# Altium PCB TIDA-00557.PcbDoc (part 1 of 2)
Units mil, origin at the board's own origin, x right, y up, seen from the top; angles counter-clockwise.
Board outline 3556 x 3500 mil, 2 copper layers (Top Layer, Bottom Layer), stack 62 mil thick; 145 components, 107 nets, 402 pads, 185 vias.
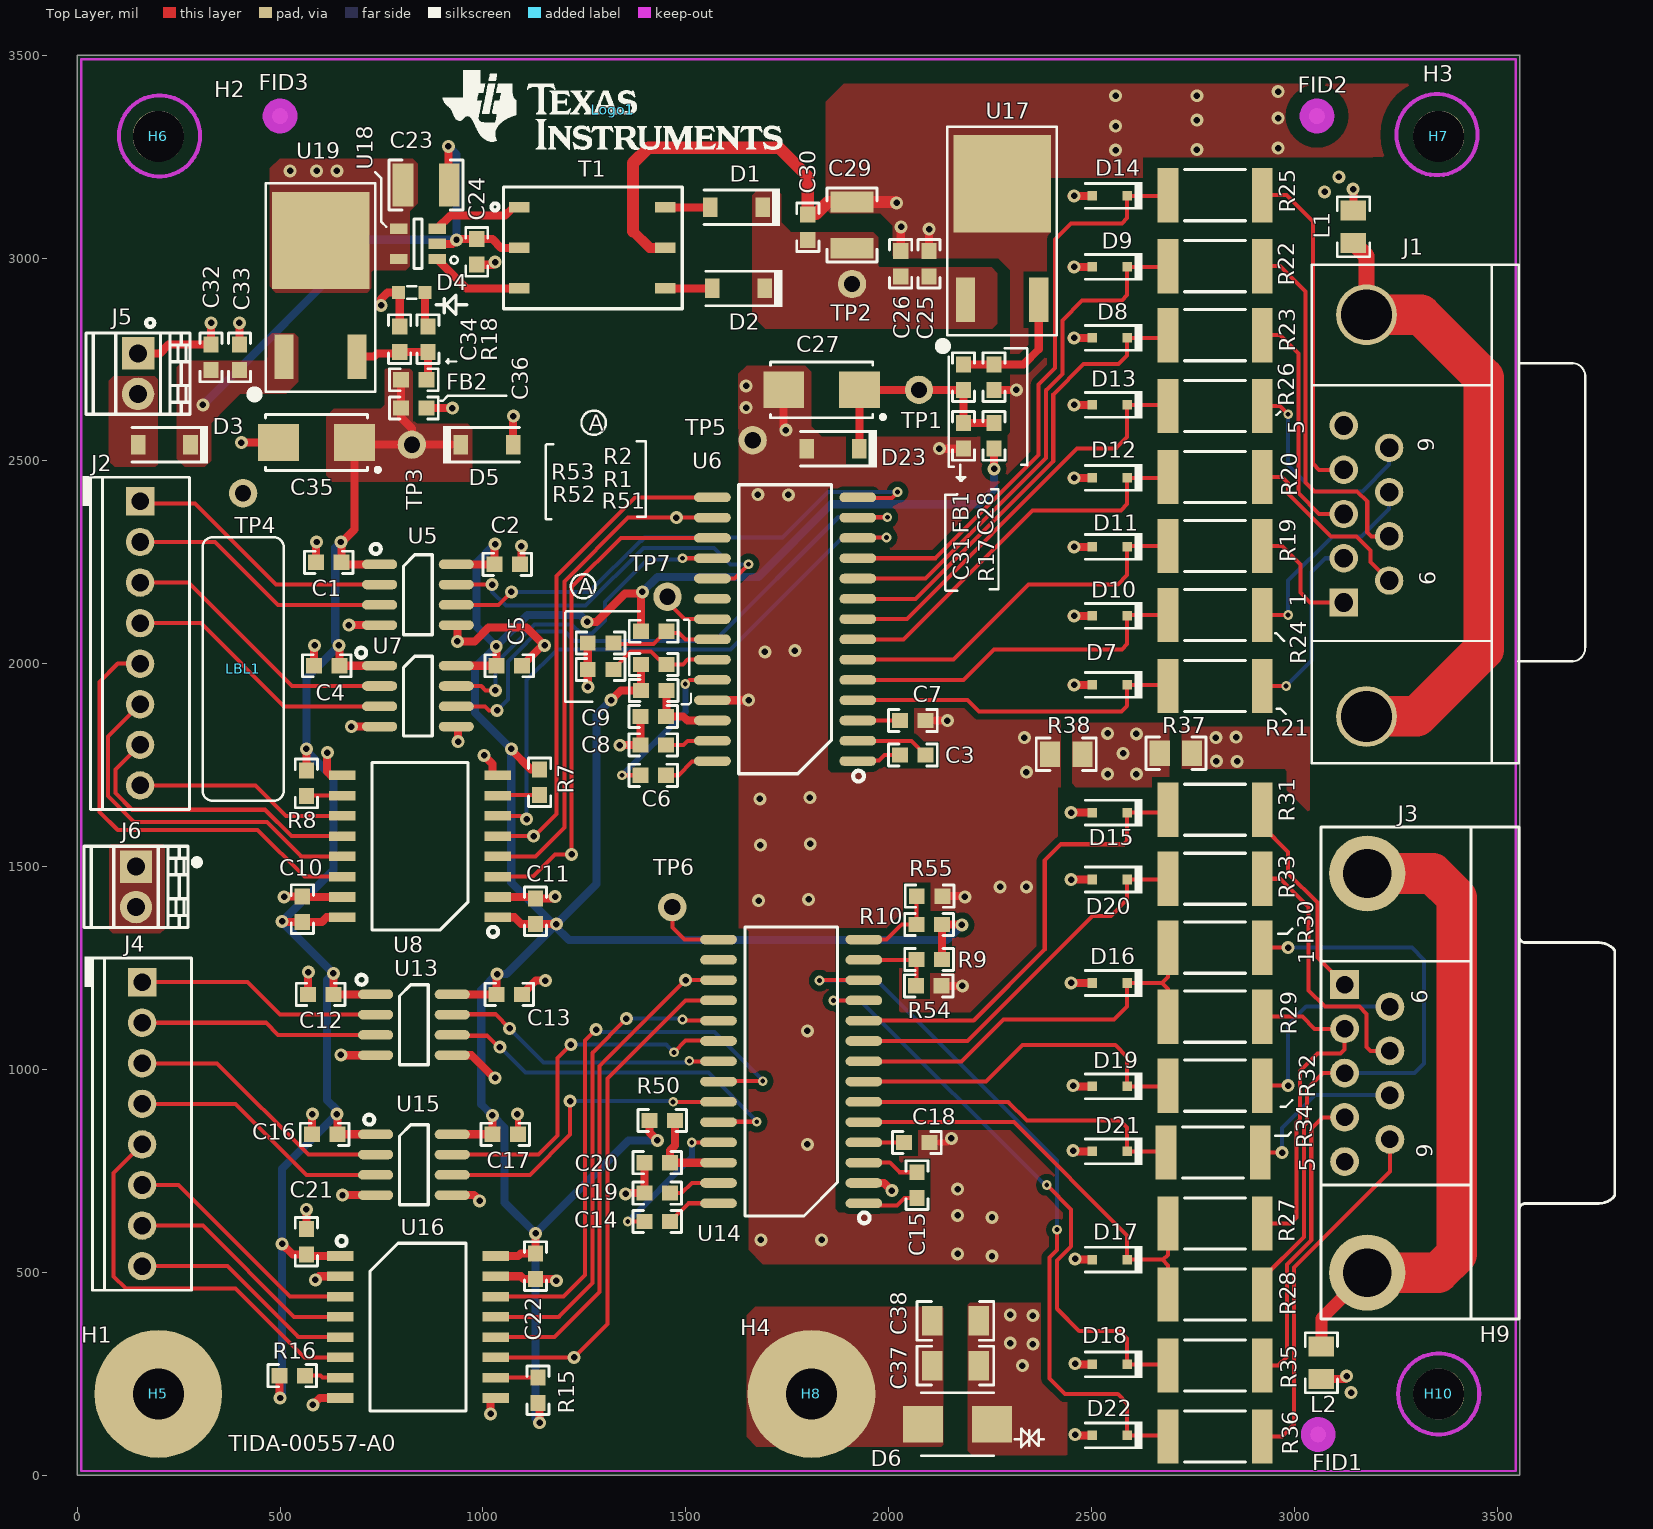
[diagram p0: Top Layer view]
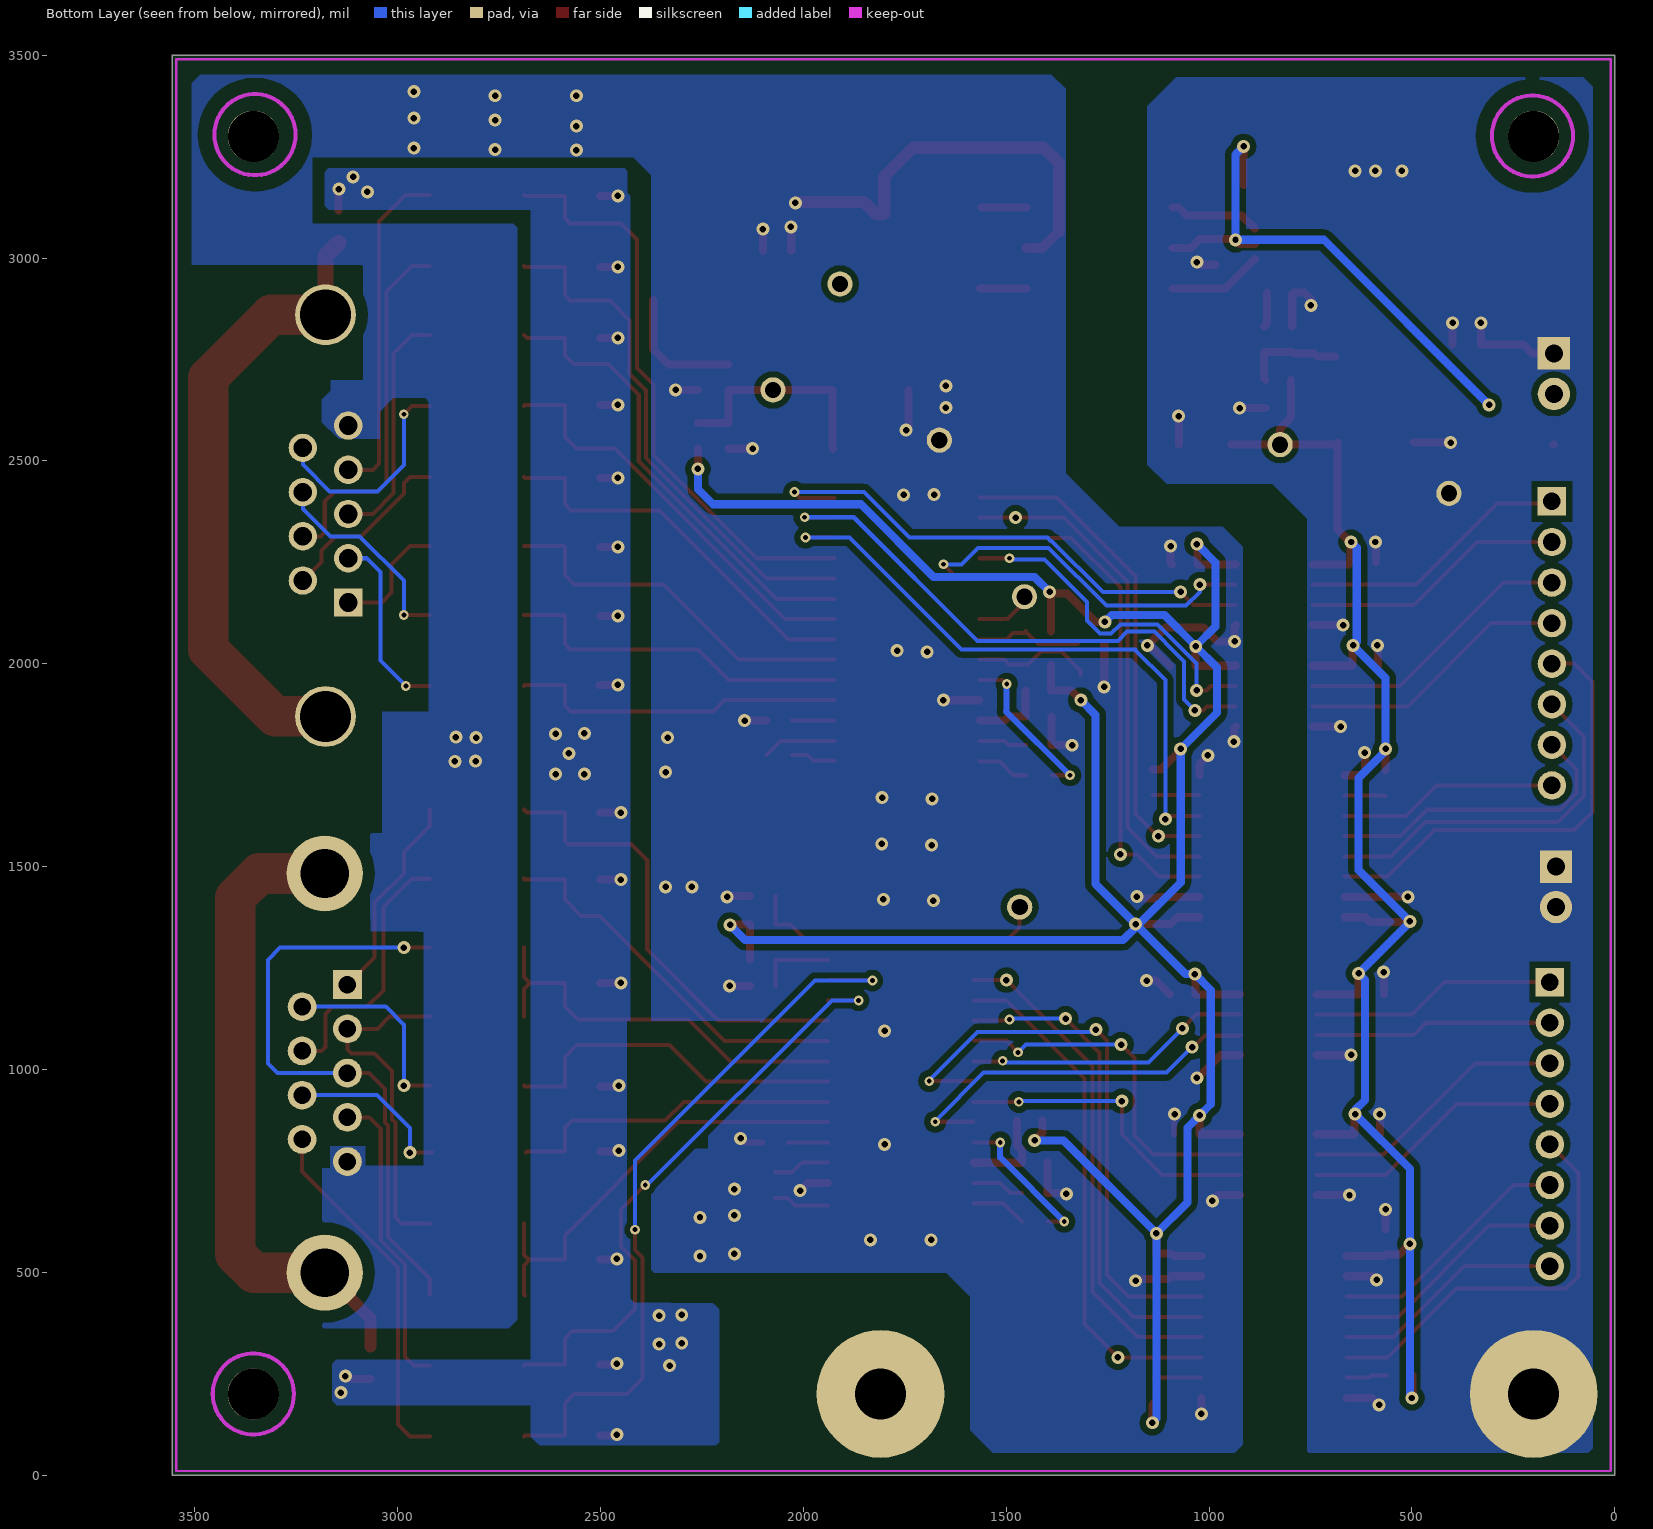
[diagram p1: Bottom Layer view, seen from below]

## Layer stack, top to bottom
Top Solder: solder mask 0.4, Solder Resist, Dk 3.5
Top Layer: signal copper 1.4
Dielectric1: core 59.2, FR-4, Dk 4.8
Bottom Layer: signal copper 1.4
Bottom Solder: solder mask 0.4, Solder Resist, Dk 3.5

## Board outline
0,0 3556,0 3556,3500 0,3500

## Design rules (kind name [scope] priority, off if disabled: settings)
AcuteAngle [All] p1: minimum=4.50000000000000E+0001 checktracksonly=FALSE
AssemblyTestPointUsage [All] p1: valid=2
Clearance Clearance_3 [InNet('NetJ3_10') vs InNet('GND2')] p1: gap=30
Clearance Clearance_2 [InNet('NetJ1_10') vs InNet('GND2')] p2: gap=30
Clearance Clearance_poly_earth [InPolygon vs InNetClass('earth')] p3: gap=100
Clearance "Bord edge_to_poly" [IsBoardOutline vs InPolygon] p4: gap=50
Clearance "MONT_HOLE_TO _POLY" [IsKeepOut vs InPolygon] p5: gap=35
Clearance Clearance_poly_to_all [InPolygon] p6: gap=15
Clearance "Clearance_Poly to Poly" [InPoly vs InPoly] p7: gap=25
Clearance [InPolygon vs (OnLayer('Keep-Out Layer'))] p8: gap=40
Clearance "Clearance_VIA TO VIA" [IsVia vs IsVia] p9: gap=8
Clearance "Clearance_Via to SMD" [IsVia vs IsSMTPin] p10: gap=8
Clearance Clearance_1 [All] p11: gap=8
ComponentClearance ComponentClearance_Logo [InComponentClass('Logo')] p1: gap=50 collisioncheckmode=3 verticalgap=10 showdistances=FALSE
ComponentClearance ComponentClearance_ScrewToNut [(HasFootprint('NY PMS 440 0025 PH')) vs (HasFootprint('Keystone_1902C'))] p2: gap=5 collisioncheckmode=3 verticalgap=10 showdistances=FALSE
ComponentClearance ComponentClearance_MountingHoles [InComponentClass('Mounting Holes')] p3: gap=250 collisioncheckmode=3 verticalgap=100000 showdistances=FALSE
ComponentClearance ComponentClearance_SmallPassives [HasFootprint('0201*') or HasFootprint('0402*') or HasFootprint('0508') or HasFootprint('0603*') or HasFootprint('0612') or HasFootprint('0805*') or HasFootprint('0815*') or HasFootprint('0830*') or HasFootprint('1206*') or HasFootprint('1210*') or HasFootprint('1808*') or HasFootprint('1812*') or HasFootprint('1825*') or HasFootprint('2010*') or HasFootprint('2220*') or HasFootprint('2225*') or HasFootprint('2512*') or HasFootprint('2728*') or HasFootprint('3518*') vs HasFootprint('0201*') or HasFootprint('0402*') or HasFootprint('0508') or HasFootprint('0603*') or HasFootprint('0612') or HasFootprint('0805*') or HasFootprint('0815*') or HasFootprint('0830*') or HasFootprint('1206*') or HasFootprint('1210*') or HasFootprint('1808*') or HasFootprint('1812*') or HasFootprint('1825*') or HasFootprint('2010*') or HasFootprint('2220*') or HasFootprint('2225*') or HasFootprint('2512*') or HasFootprint('2728*') or HasFootprint('3518*')] p4: gap=20 collisioncheckmode=3 verticalgap=10 showdistances=FALSE
ComponentClearance ComponentClearance_THtoSMT [IsThruComponent vs IsSMTComponent] p5: gap=100 collisioncheckmode=3 verticalgap=30 showdistances=FALSE
ComponentClearance ComponentClearance_THtoTH [IsThruComponent vs IsThruComponent] p6: gap=118.11 collisioncheckmode=3 verticalgap=30 showdistances=FALSE
ComponentClearance [All] p7: gap=40 collisioncheckmode=3 verticalgap=10 showdistances=FALSE
DiffPairsRouting [All] p1: maxlimit=100 minlimit=10 mostfreqgap=10 toplayer_minwidth=15 toplayer_maxwidth=15 toplayer_prefwidth=15 bottomlayer_minwidth=15 bottomlayer_maxwidth=15 bottomlayer_prefwidth=15 maxuncoupledlength=1000
FabricationTestPointUsage TestPointUsage [All] p1: valid=2 allowmultiple=FALSE
FabricationTestpoint Testpoint [All] p1: side=3 testpointundercomponent=TRUE minsize=40 maxsize=100 preferedsize=60 minholesize=0 maxholesize=40 preferedholesize=32 testpointgrid=1 allowsidetop=TRUE allowsidebottom=TRUE usegrid=TRUE gridtolerance=0.01
FanoutControl Fanout_LCC [IsLCC] p1: bgadir=Out bgaviamode=Centered fanoutstyle=Auto fanoutdirection=Alternating viagrid=1 // Fanout_LCC (Default Rule)
FanoutControl Fanout_BGA [IsBGA] p2: bgadir=Out bgaviamode=Centered fanoutstyle=Auto fanoutdirection=Alternating viagrid=1 // Fanout_BGA (Default Rule)
FanoutControl Fanout_Default [All] p4: bgadir=Out bgaviamode=Centered fanoutstyle=Auto fanoutdirection=Alternating viagrid=1 // Fanout_Default (Default Rule)
FanoutControl Fanout_Small [(CompPinCount < 5)] p5: bgadir=Out bgaviamode=Centered fanoutstyle=Auto fanoutdirection=OutThenIn viagrid=1 // Fanout_Small (Default Rule)
HoleSize [All] p1: absolutevalues=TRUE maxlimit=251 minlimit=7.8 maxpercent=80.000 minpercent=20.000
MinimumAnnularRing MinimumAnnularRing_ThermalPadVias [IsVia and InAnyComponent] p1: minimumring=5.91
MinimumAnnularRing [All] p2: minimumring=6
MinimumSolderMaskSliver MinimumSolderMaskSliver_Logo [InComponentClass('Logo') vs InComponentClass('Logo')] p1: minsoldermaskwidth=0.7
MinimumSolderMaskSliver [All] p2: minsoldermaskwidth=3.94
PlaneConnect [All] p1: planeconnectstyle=Direct reliefexpansion=10 reliefentries=4 reliefconductorwidth=10 reliefairgap=10
PolygonConnect [All] p1: connectstyle=Direct reliefconductorwidth=10 reliefentries=4 polygonreliefangle="90 Angle" airgapwidth=10
RoutingVias RoutingVias_PWR [InNetClass('Power')] p1: holewidth=16 width=32 viastyle="Through Hole" minholewidth=16 minwidth=32 maxholewidth=16 maxwidth=32
RoutingVias [(InNetClass('All Nets'))] p2: holewidth=12 width=24 viastyle="Through Hole" minholewidth=12 minwidth=24 maxholewidth=16 maxwidth=32
RoutingVias ThermalPadVias [IsVia and InAnyComponent] p3: holewidth=7.87 width=19.68 viastyle="Through Hole" minholewidth=7.87 minwidth=19.68 maxholewidth=12.99 maxwidth=23.62
SMDToCorner [All] p1: distance=30000
SilkToSilkClearance [All] p1: silktosilkclearance=5
SilkToSolderMaskClearance SilkscreenOverComponentPads [IsPad] p1 off: minsilkscreentomaskgap=5 clearancetoexposedcopper=TRUE
SolderMaskExpansion [All] p1: expansion=2.5
UnpouredPolygon [All] p1: allowunpoured=FALSE
Width Width_PWR [InNetClass('Power')] p1: maxlimit=100 minlimit=10 preferedwidth=20
Width [All] p2: maxlimit=100 minlimit=8 preferedwidth=8 checkconnectedcopper=TRUE
15 further rules are at their usual default settings.

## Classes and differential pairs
component class "Page4 Power Supply": C23 C24 C25 C26 C27 C28 C29 C30 C31 C32 C33 C34 C35 C36 C37 C38 D1 D2 D3 D4 D5 D6 D23 FB1 FB2 J5 R17 R18 T1 TP1 TP2 TP3 TP4 TP5 U17 U18 U19
component class "Page5 Hardware_ANSI-B": FID1 FID2 FID3 H1 H2 H3 H4 H5 H6 H7 H8 H9 H10 LBL1 Logo1 ZZ1 ZZ2 ZZ3 ZZ4
component class Logo: Logo1
component class "Page2 DTE-DCE": C1 C2 C3 C4 C5 C6 C7 C8 C9 C10 C11 D7 D8 D9 D10 D11 D12 D13 D14 J1 J2 J6 L1 R1 R2 R7 R8 R19 R20 R21 R22 R23 R24 R25 R26 R51 R52 R53 TP7 U5 U6 U7 U8
component class "Page3 DCE-DTE": C12 C13 C14 C15 C16 C17 C18 C19 C20 C21 C22 D15 D16 D17 D18 D19 D20 D21 D22 J3 J4 L2 R9 R10 R15 R16 R27 R28 R29 R30 R31 R32 R33 R34 R35 R36 R37 R38 R50 R54 R55 TP6 U13 U14 U15 U16
component class AssemblyNote: ZZ1 ZZ2 ZZ3 ZZ4
component class Label: LBL1
component class FiducialMark: FID1 FID2 FID3
component class "Mounting Holes": H1 H2 H3 H4 H9
net class Power: +5V +6V_VDC GND1 GND2 VCC1 VCC2

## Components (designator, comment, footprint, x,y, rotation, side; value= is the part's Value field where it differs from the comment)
C1 "C0603C104K5RACTU" 0603 620,2250 r180 top
C2 "C0603C104K5RACTU" 0603 1060,2245 r0 top
C3 "C0603C104K5RACTU" 0603 2060,1775 r0 top
C4 "C0603C104K5RACTU" 0603 615,1995 r180 top
C5 "C0603C104K5RACTU" 0603 1065,1995 r0 top
C6 "C0603C104K5RACTU" 0603 1420,1725 r180 top
C7 "C0603C104K5RACTU" 0603 2060,1860 r0 top
C8 "C0603C104K5RACTU" 0603 1420,1800 r180 top
C9 "C0603C104K5RACTU" 0603 1420,1870 r180 top
C10 "C0603C104K5RACTU" 0603 555,1395 r90 top
C11 "C0603C104K5RACTU" 0603 1130,1390 r90 top
C12 "C0603C104K5RACTU" 0603 600,1185 r180 top
C13 "C0603C104K5RACTU" 0603 1065,1185 r0 top
C14 "C0603C104K5RACTU" 0603 1430,625 r180 top
C15 "C0603C104K5RACTU" 0603 2070,715 r90 top
C16 "C0603C104K5RACTU" 0603 610,840 r180 top
C17 "C0603C104K5RACTU" 0603 1055,840 r0 top
C18 "C0603C104K5RACTU" 0603 2070,820 r0 top
C19 "C0603C104K5RACTU" 0603 1430,695 r180 top
C20 "C0603C104K5RACTU" 0603 1430,770 r180 top
C21 "C0603C104K5RACTU" 0603 565,575 r90 top
C22 "C0603C104K5RACTU" 0603 1130,515 r270 top
C23 "" 1210 860,3180 r0 top
C24 "" 0603 985,3015 r90 top
C25 "C1608X7R1C105K" 0603 2100,2986 r90 top
C26 "C0603C104K5RACTU" 0603 2030,2986 r90 top
C27 "293D475X9035C2TE3" 6032-28 1835,2675 r180 top
C28 "C1608X7R1C105K" 0603 2260,2706.5 r270 top
C29 "" 1210 1910,3081 r90 top
C30 "" 0603 1801,3076 r90 top
C31 "C0603C104K5RACTU" 0603 2185,2561.5 r270 top
C32 "C1608X7R1C105K" 0603 330,2755 r90 top
C33 "C0603C104K5RACTU" 0603 400,2755 r90 top
C34 "C1608X7R1C105K" 0603 795,2800 r90 top
C35 "293D475X9035C2TE3" 6032-28 590,2545 r180 top
C36 "C0603C104K5RACTU" 0603 830,2630 r0 top
C37 "202R18W102KV4E" 1206 2165,270 r180 top
C38 "202R18W102KV4E" 1206 2165,380 r180 top
D1 "B0520LW-7-F" SOD-123 1625,3125 r180 top
D2 "B0520LW-7-F" SOD-123 1630,2925 r180 top
D3 "B0520LW-7-F" SOD-123 215,2540 r180 top
D4 "LED_LG L29K-G2J1-24-Z" LED0603AA 825,2915 r0 top
D5 "MMSZ5228B-7-F" sod-123 1010,2540 r0 top
D6 "SMBJ18CA" DIO_SMB_BIAAAA 2170,125 r180 top
D7 "CDSOD323-T12C" sod-323 2545,1947.99 r180 top
D8 "CDSOD323-T12C" sod-323 2545,2802.99 r180 top
D9 "CDSOD323-T12C" sod-323 2545,2977.99 r180 top
D10 "CDSOD323-T12C" sod-323 2545,2117.99 r180 top
D11 "CDSOD323-T12C" sod-323 2545,2287.99 r180 top
D12 "CDSOD323-T12C" sod-323 2545,2457.99 r180 top
D13 "CDSOD323-T12C" sod-323 2545,2637.99 r180 top
D14 "CDSOD323-T12C" sod-323 2545,3152.99 r180 top
D15 "CDSOD323-T12C" sod-323 2545,1632.99 r180 top
D16 "CDSOD323-T12C" sod-323 2545,1212.99 r180 top
D17 "CDSOD323-T12C" sod-323 2545,530.99 r180 top
D18 "CDSOD323-T12C" sod-323 2545,272.99 r180 top
D19 "CDSOD323-T12C" sod-323 2545,957.99 r180 top
D20 "CDSOD323-T12C" sod-323 2545,1467.99 r180 top
D21 "CDSOD323-T12C" sod-323 2545,797.99 r180 top
D22 "CDSOD323-T12C" sod-323 2545,97.99 r180 top
D23 "MMSZ5228B-7-F" sod-123 1863,2530 r180 top
FB1 "1000 OHM" 0603 2185,2706.5 r270 top
FB2 "1000 OHM" 0603 830,2700 r180 top
FID1 "Fiducial" Fiducial10-20 3059,100 r90 top
FID2 "Fiducial" Fiducial10-20 3056,3350 r90 top
FID3 "Fiducial" Fiducial10-20 500,3350 r90 top
H1 "NY PMS 440 0025 PH" "NY PMS 440 0025 PH"#1 200,200 r0 top
H2 "NY PMS 440 0025 PH" "NY PMS 440 0025 PH"#2 200,3300 r0 top
H3 "NY PMS 440 0025 PH" "NY PMS 440 0025 PH"#2 3356,3300 r0 top
H4 "NY PMS 440 0025 PH" "NY PMS 440 0025 PH"#1 1810,200 r0 top
H5 "1902C" Keystone_1902C 200,200 r0 top
H6 "1902C" Keystone_1902C 200,3300 r0 top
H7 "1902C" Keystone_1902C 3356,3300 r0 top
H8 "1902C" Keystone_1902C 1810,200 r0 top
H9 "NY PMS 440 0025 PH" "NY PMS 440 0025 PH"#2 3356,200 r0 top (schematic designator H3)
H10 "1902C" Keystone_1902C 3356,200 r0 top
J1 "CONN_DB9_RA" DB9_RA 3122,2151 r90 top
J2 "1725711" CONN_1725711 155,2050 r270 top
J3 "182-009-213R171" NORCOMP_182-009-213R171 3554,991 r270 top
J4 "1725711" CONN_1725711 160,865 r270 top
J5 "CON-OSTVN02A150" CN2_MTB_P100_PD80_D1.1_S5.54X6.5_STACK 150,2715 r270 top
J6 "CON-OSTVN02A150" CN2_MTB_P100_PD80_D1.1_S5.54X6.5_STACK 145,1450 r270 top
L1 "BLM21AG121SN1D" 0805_HV 3146,3077 r90 top
L2 "BLM21AG121SN1D" 0805_HV 3067,277 r270 top
LBL1 "Size: 0.65\" x 0.20 \"" Label_650x200 409,1987 r90 top
Logo1 "Texas Instruments" TI_Stacked_Overlay_Small 1320,3365 r0 top
R1 "CRCW060310K0FKEA" 0603 1421,1998 r180 top
R2 "CRCW060310K0FKEA" 0603 1421,2080 r180 top
R7 "CRCW060310K0FKEA" 0603 1140,1708 r90 top
R8 "CRCW060310K0FKEA" 0603 565,1705 r90 top
R9 "CRCW060310K0FKEA" 0603 2100,1271 r0 top
R10 "CRCW060310K0FKEA" 0603 2100,1357 r0 top
R15 "CRCW060310K0FKEA" 0603 1136,209 r270 top
R16 "CRCW060310K0FKEA" 0603 530,245 r180 top
R17 "CRCW06030000Z0EA" 0603 2260,2561.5 r270 top
R18 "CRCW0603300RJNEA" 0603 865,2800 r270 top
R19 "RPC2512JT22R0" 2512 2805,2290 r0 top
R20 "RPC2512JT22R0" 2512 2805,2460 r0 top
R21 "RPC2512JT22R0" 2512 2805,1945 r0 top
R22 "RPC2512JT22R0" 2512 2805,2980 r0 top
R23 "RPC2512JT22R0" 2512 2805,2810 r0 top
R24 "RPC2512JT22R0" 2512 2805,2120 r0 top
R25 "RPC2512JT22R0" 2512 2805,3155 r0 top
R26 "RPC2512JT22R0" 2512 2805,2635 r0 top
R27 "DNP" 2512 2805,620 r0 top
R28 "RPC2512JT22R0" 2512 2805,445 r0 top
R29 "RPC2512JT22R0" 2512 2805,1130 r0 top
R30 "DNP" 2512 2805,1300 r0 top
R31 "RPC2512JT22R0" 2512 2805,1640 r180 top
R32 "RPC2512JT22R0" 2512 2805,960 r180 top
R33 "RPC2512JT22R0" 2512 2805,1470 r180 top
R34 "RPC2512JT22R0" 2512 2800,795 r180 top
R35 "RPC2512JT22R0" 2512 2805,270 r180 top
R36 "RPC2512JT22R0" 2512 2805,95 r180 top
R37 "CRCW08050000Z0EA" 0805_HV 2708.19,1779.29 r180 top
R38 "CRCW08050000Z0EA" 0805_HV 2438,1777 r0 top
R50 "CRCW06030000Z0EA" 0603 1442,874 r180 top
R51 "CRCW06030000Z0EA" 0603 1421,1934 r0 top
R52 "CRCW060310K0FKEA" 0603 1290,1986 r180 top
R53 "CRCW060310K0FKEA" 0603 1290,2051 r0 top
R54 "CRCW060310K0FKEA" 0603 2099,1206 r180 top
R55 "CRCW060310K0FKEA" 0603 2101,1427 r180 top
T1 "TRNSFMR 760390014" 760390015 1090,3125 r0 top
TP1 "TP-040_RND" TP-040_RND 2075,2675 r0 top
TP2 "TP-040_RND" TP-040_RND 1910,2936 r0 top
TP3 "TP-040_RND" TP-040_RND 825,2540 r0 top
TP4 "TP-040_RND" TP-040_RND 409,2420 r0 top
TP5 "TP-040_RND" TP-040_RND 1665,2551 r0 top
TP6 "TP-040_RND" TP-040_RND 1467,1400 r0 top
TP7 "TP-040_RND" TP-040_RND 1455,2165 r0 top
U5 "ISO7321CD" D0008A_N 840,2170 r0 top
U6 "TRS3243EIDWR" DW0028A_N 1745,2085 r180 top
U7 "ISO7321CD" D0008A_N 840,1920 r0 top
U8 "ISO7341CDWR" DW0016B_HV 845,1550 r180 top
U13 "ISO7321CD" D0008A_N 830,1110 r0 top
U14 "TRSF3238EIDWR" DW0028A_N 1760,995 r180 top
U15 "ISO7321CD" D0008A_N 830,765 r0 top
U16 "ISO7341CDWR" DW0016B_HV 840,365 r0 top
U17 "TPS7A6533QKVURQ1" KVU_1 2280,3040 r0 top
U18 "SN6501DBV" DBV0005A_N 840,3035 r180 top
U19 "TPS7A6533QKVURQ1" KVU_1 600,2900 r0 top
ZZ1 "This Assembly Note is for PCB labels only" AssemblyNoteLabel 205,5165 r0 top
ZZ2 "These assemblies are ESD sensitive, ESD precautions shall be observed." AssemblyNote 200,5075 r0 top
ZZ3 "These assemblies must be clean and free from flux and all contaminants. Use of no clean flux is not acceptable." AssemblyNote 200,4990 r0 top
ZZ4 "These assemblies must comply with workmanship standards IPC-A-610 Class 2, unless otherwise specified." AssemblyNote 200,4910 r0 top

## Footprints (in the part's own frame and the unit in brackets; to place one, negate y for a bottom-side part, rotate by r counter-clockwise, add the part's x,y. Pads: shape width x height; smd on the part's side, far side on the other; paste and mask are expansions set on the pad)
0603 [mm] "0603 from SM-752 data"
  rect 1x0.95 smd: 1(-0.8,0) 2(0.8,0)
  silkscreen extent -1.52,-0.69 1.52,0.69, body extent -0.87,-0.47 0.87,0.47, height 0.85
0805_HV [mil] "0805 with 30mil clearance between pads"
  rect 50x63 smd: 1(-40,0) 2(40,0)
  silkscreen extent -74,-40 74,40, body extent -43,-29 43,29, height 43
1206 [mm] "1206 from SM-752 data"
  rect 1.3x1.85 smd: 1(-1.45,0) 2(1.45,0)
  silkscreen extent -2.4,-1.21 2.4,1.21, body extent -1.7,-0.9 1.7,0.9, height 1.35
1210 [mm] "1210 from SM-752 data"
  rect 1.3x2.7 smd: 1(-1.45,0) 2(1.45,0)
  silkscreen extent -2.32,-1.57 2.32,1.57, body extent -1.7,-1.35 1.7,1.35, height 1.35
2512 [mm] "Chip Resistor, Body 6.3x3.2mm, IPC Medium Density"
  rect 1.3x3.4 smd: 1(-2.95,0) 2(2.95,0)
  silkscreen extent -1.9,-1.6 1.9,1.6, body extent -3.22,-1.67 3.22,1.67, height 0.71
6032-28 [mm] "Medium Density IPC based on Vishay Sprague 293D datasheet."
  rect 2.55x2.3 smd: 1(-2.375,0) 2(2.375,0)
  silkscreen extent -3.96,-1.75 3.2,1.82, body extent -3.15,-1.75 3.15,1.75, height 2.8
760390015 [mm]
  rect 1.27x0.66 smd: 1(0,0) 2(0,-2.54) 3(0,-5.08) 4(9.14,-5.08) 5(9.14,-2.54) 6(9.14,0)
  silkscreen extent -1.75,-6.35 10.2,1.27, body extent -1,-6.4 10.2,1.2, height 4.2
AssemblyNote [mil] "Assembly Note"
AssemblyNoteLabel [mil] "Assembly Note for PCB Labels"
CN2_MTB_P100_PD80_D1.1_S5.54X6.5_STACK [mil]
  rect 80x80 / inner round 80 / far side rect 80x80 hole 44: 1(-50,0)
  round 80 hole 44: 2(50,0)
  silkscreen extent -135,-128 100,128
CONN_1725711 [mm] "Phoenix Contact"
  rect 1.78x1.78 hole 1.1: 1(-8.89,0)
  round 1.78 hole 1.1: 2(-6.35,0) 3(-3.81,0) 4(-1.27,0) 5(1.27,0) 6(3.81,0) 7(6.35,0) 8(8.89,0)
  silkscreen extent -10.49,-3.6 10.4,3.1, body extent -10.39,-3.1 10.39,3.1, height 8.52
D0008A_N [mm] "SOIC, 8-Leads, Body 4.9x3.9mm, Pitch 1.27mm, IPC Medium Density"
  oval 2.2x0.6 smd: 1(-2.4,1.905) 2(-2.4,0.635) 3(-2.4,-0.635) 4(-2.4,-1.905) 5(2.4,-1.905) 6(2.4,-0.635) 7(2.4,0.635) 8(2.4,1.905)
  silkscreen extent -0.9,-2.5 0.9,2.5, body extent -3,-2.45 3,2.45, height 1.63
DB9_RA [mil]
  rect 70x70 hole 46: 1(0,0)
  round 70 hole 46: 2(109,0) 3(218,0) 4(327,0) 5(436,0) 6(54,-112) 7(163,-112) 8(272,-112) 9(381,-112)
  round 150 hole 125: 10(709,-56) 11(-281,-56)
  silkscreen extent -396,-595 832,79
DBV0005A_N [mm] "SOT23, 5-Leads, Body 2.9x1.6mm, Pitch 0.95mm, Lead Span 2.8mm, IPC Medium Density"
  rect 1.1x0.65 smd: 1(-1.2,0.95) 2(-1.2,0) 3(-1.2,-0.95) 4(1.2,-0.95) 5(1.2,0.95)
  silkscreen extent -0.25,-1.55 0.25,1.55, body extent -1.42,-1.46 1.42,1.46, height 1.08
DIO_SMB_BIAAAA [mm]
  rect 2.5x2.3 smd: 1(-2.15,0) 2(2.15,0)
  silkscreen extent -5.41,-1.97 2.29,1.97
DW0016B_HV [mm] "High voltage version of DW0016B"
  rect 1.65x0.6 smd: 1(-4.875,4.445) 2(-4.875,3.175) 3(-4.875,1.905) 4(-4.875,0.635) 5(-4.875,-0.635) 6(-4.875,-1.905) 7(-4.875,-3.175) 8(-4.875,-4.445) 9(4.875,-4.445) 10(4.875,-3.175) 11(4.875,-1.905) 12(4.875,-0.635) 13(4.875,0.635) 14(4.875,1.905) 15(4.875,3.175) 16(4.875,4.445)
  silkscreen extent -3,-5.25 3,5.25, body extent -5.14,-5.13 5.14,5.13, height 2.5
DW0028A_N [mm] "SOIC, 28-Leads, Body 17.9x7.5mm, Pitch 1.27mm, IPC Medium Density"
  oval 2.3x0.6 smd: 1(-4.55,8.255) 2(-4.55,6.985) 3(-4.55,5.715) 4(-4.55,4.445) 5(-4.55,3.175) 6(-4.55,1.905) 7(-4.55,0.635) 8(-4.55,-0.635) 9(-4.55,-1.905) 10(-4.55,-3.175) 11(-4.55,-4.445) 12(-4.55,-5.715) 13(-4.55,-6.985) 14(-4.55,-8.255) 15(4.55,-8.255) 16(4.55,-6.985) 17(4.55,-5.715) 18(4.55,-4.445) 19(4.55,-3.175) 20(4.55,-1.905) 21(4.55,-0.635) 22(4.55,0.635) 23(4.55,1.905) 24(4.55,3.175) 25(4.55,4.445) 26(4.55,5.715) 27(4.55,6.985) 28(4.55,8.255)
  silkscreen extent -2.9,-9.05 2.9,9.05, body extent -5.16,-8.95 5.16,8.95, height 2.55
Fiducial10-20 [mm]
  round 1 smd mask+0.5: 1(0,0)
  Top Layer keep-out circle w1.178: c0,0 r0.5
Keystone_1902C [mil] "Hex Standoff, 4-40 threaded, nylon"
  round 1 on Mech3: 0(0,0)
  body extent -145,-126 146,126, height 501
KVU_1 [mm]
  rect 1.2x2.8 smd: 1(-2.29,-3.635) 3(2.29,-3.635)
  rect 6.096x6.096 smd: 2(0,3.635)
  silkscreen extent -3.77,-6.58 3.43,7.22
Label_650x200 [mil] "Thermal Transfer Label"
  round 1 on Mech13: 0(0,0)
  silkscreen extent -325,-100 325,100, body extent -326,-101 326,101, height 1
LED0603AA [mil]
  rect 32x32 smd: 1(-32.48,0) 2(32.48,0)
  silkscreen extent -11,-53 135,16
NORCOMP_182-009-213R171 [mm] "Connector; D Subminiature 9 Position; Right Angle"
  rect 1.8x1.8 hole 1.092: 1(-5.54,-10.92)
  round 1.8 hole 1.092: 2(-2.77,-10.92) 3(0,-10.92) 4(2.77,-10.92) 5(5.54,-10.92) 6(-4.155,-8.08) 7(-1.385,-8.08) 8(1.385,-8.08) 9(4.155,-8.08)
  round 4.76 hole 3.05: 10(-12.495,-9.5) 11(12.495,-9.5)
  silkscreen extent -15.4,-12.4 15.4,6, body extent -15.41,-12.98 15.41,6.1, height 12.55
"NY PMS 440 0025 PH"#1 [mm] "4-40 nylon screw and mounting hole"
  round 8 hole 3.2: 1(0,0)
  body extent -3.3,-3.3 3.3,3.3, height 2.69
"NY PMS 440 0025 PH"#2 [mm] "4-40 nylon screw and mounting hole"
  round 3.2 hole 3.2 unplated mask+0.127: 1(0,0)
  body extent -3.3,-3.3 3.3,3.3, height 2.69
SOD-123 [mm] "On Semi recommended land pattern"
  rect 0.915x1.22 smd: 1(-1.637,0) 2(1.637,0)
  silkscreen extent -2.74,-1.17 2.03,1.17, body extent -1.93,-0.9 1.93,0.9, height 1.35
sod-123 [mm] "On Semi recommended land pattern"
  rect 0.915x1.22 smd: 1(-1.637,0) 2(1.637,0)
  silkscreen extent -2.74,-1.17 2.03,1.17, body extent -1.93,-0.9 1.93,0.9, height 1.35
sod-323 [mm] "NXP recommended land pattern"
  rect 0.6x0.6 smd paste-0.05: 1(-1.1,0) 2(1.1,0)
  silkscreen extent -2.06,-0.86 1.53,0.86, body extent -1.3,-0.67 1.3,0.68, height 1.1
TI_Stacked_Overlay_Small [mil]
  silkscreen extent -418,-98 418,98
TP-040_RND [mil]
  round 70 / inner round 62 / far side round 62 hole 40: 1(0,0)

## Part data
C1 C2 C3 C4 C5 C6 C7 C8 C9 C10 C11 C12 C13 C14 C15 C16 C17 C18 C19 C20 C21 C22 C26 C31 C33 C36: "CAP, CERM, 0.1uF, 50V, +/-10%, X7R, 0603"
C23 C29: library part GMK325AB7106MM-T, "CAP, CERM, 10uF, 35V, +/-20%, X7R, 1210"
C24 C30: library part C0603C104K5RACTU, "CAP, CERM, 0.1uF, 50V, +/-10%, X7R, 0603"
C25 C28 C32 C34: "CAP, CERM, 1uF, 16V, +/-10%, X7R, 0603"
C27 C35: "CAP, TA, 4.7uF, 35V, +/-10%, 1.9 ohm, SMD"
C37 C38: "CAP, CERM, 1000pF, 2KV 10% X7R 1206"
D1 D2 D3: library part MBR0520LT1G, "Diode, Schottky, 20V, 0.5A, SOD-123"
D4: "LED SmartLED Green 570NM"
D5 D23: library part 1SMB5915BT3G, "DIODE ZENER 3.9V 500MW SOD123"
D6: "TVS 18 VOLT 600 WATT BI-DIR SMB"
D7 D8 D9 D10 D11 D12 D13 D14 D15 D16 D17 D18 D19 D20 D21 D22: library part CDSOD323-T15SC, "Diode, TVS, ARRAY, 19V, SOD323"
FB1 FB2: library part MMZ1608B102C, "FERRITE CHIP 1000 OHM 300MA 0603"
FID1 FID2 FID3: "Fiducial mark.  There is nothing to buy or mount."
H1 H2 H3 H4 H9: "Machine Screw, Round, #4-40 x 1/4, Nylon, Philips panhead"
H5 H6 H7 H8 H10: "Standoff, Hex, 0.5\"L #4-40 Nylon"
J1: "Connector, 9-pin D, Right Angle, Male"
J2 J4: "Terminal Block, 8x1, 2.54 mm, TH"
J3: "CONN DB9 FEMALE R/A SOLDER TH"
J5 J6: "CONN TERM BLOCK 2.54MM 2POS PCB"
L1 L2: "Ferrite Bead, 120 ohm @ 100 MHz, 0.8 A, 0805"
LBL1: library part THT-14-423-10, "Thermal Transfer Printable Labels, 0.650\" W x 0.200\" H - 10,000 per roll"
Logo1: library part TI_Logo, "Texas Instrument Corporate Signature"
R1 R2 R7 R8 R9 R10 R15 R16 R52 R53 R54 R55: "RES, 10.0k ohm, 1%, 0.1W, 0603"
R17: "RES, 0 ohm, 5%, 0.1W, 0603"
R18: "RES, 300 ohm, 5%, 0.1W, 0603"
R19 R20 R21 R22 R23 R24 R25 R26 R28 R29 R31 R32 R33 R34 R35 R36: library part CRCW251210R0FKEG, "RES SMD 22 OHM 5% 1.5W 2512"
R27 R30: library part CRCW251210R0FKEG
R37 R38: "RES, 0, 5%, 0.125 W, 0805"
R50 R51: "RES, 0, 5%, 0.1 W, 0603"
T1: library part "TRNSFMR 760390015", "Transformer 475uH SMD"
TP1 TP2 TP3 TP4 TP5 TP6 TP7: "Test Point, O.040 Hole"
U5 U7 U13 U15: "IC, ISOLATOR DGTL 2CH 1/1, SOIC-8, ROHS"
U6: "3-V to 5.5-V Multichannel RS-232 Line Driver / Receiver with ±15-kV IEC ESD Protection, -40 to 85 degC, 28-Pin SOIC (DW), Green (RoHS & no Sb/Br)"
U8 U16: "Robust EMC, Low Power, Quad-Channel Digital Isolators, DW0016B"
U14: "3-V to 5.5-V Multichannel RS-232 Line Driver / Receiver with ±15-kV ESD (HBM) Protection, -40 to 85 degC, 28-Pin SOIC (DW),  Green (RoHS & no Sb/Br)"
U17 U19: "IC, 300-mA 40-V LOW-DROPOUT REGULATOR WITH 25-uA QUIESCENT CURRENT"
U18: "Transformer Driver for Isolated Power Supplies, DBV0005A"
ZZ1: library part AssemblyNoteLabel
ZZ2 ZZ3 ZZ4: library part AssemblyNote

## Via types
v1: diameter 32, hole 16, Top Layer to Bottom Layer, 163 vias
v2: diameter 24, hole 12, Top Layer to Bottom Layer, 22 vias

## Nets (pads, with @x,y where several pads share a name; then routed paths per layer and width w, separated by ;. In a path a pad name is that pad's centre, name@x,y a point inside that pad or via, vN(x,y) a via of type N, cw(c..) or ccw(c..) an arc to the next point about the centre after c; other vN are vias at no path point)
+5V: C23.2 C24.2 C32.1 C33.1 D3.1 T1.2 U18.2 U19.1 | length 1343.3
  Top Layer w20: U18.2@887.24,3035 925,3035 v1(935,3045) 936.5,3046.5 C24.2@985,3046.5 1023.5,3046.5 1045,3025 T1.2@1090,3025 ; C23.2@915,3180 v1(915,3275)
  Bottom Layer w20: v1(310,2638) 717,3045 v1(935,3045) 935,3255 v1(915,3275)
+6V_VDC: C25.1 C26.1 C29.1 C30.1 D1.1 D2.1 TP2.1 U17.1
CTS_IN: D10.1 R24.1 U6.5 | length 871.8
  Top Layer w10: U6.5@1924.13,1960 2185,1960 2260,2035 2575,2035 2588.31,2048.31 D10.1@2588.31,2117.99 2590.32,2120 R24.1@2688.86,2120
CTS_IN_1: U6.18 U7.7 | length 856.2
  Top Layer w10: U7.7@934.49,1945 996,1945 1007,1934 v1(1031,1934) ; v2(1492,2260) U6.18@1565.87,2260
  Bottom Layer w10: v1(1031,1934) 1031,2000.46 1044.54,2014 1045.01,2014 1062,2030.99 1062,2031.46 1127.54,2097 1219,2097 1242,2074 1269.01,2074 1301,2105.99 1301,2152 1406,2257 1489,2257 v2(1492,2260)
CTS_OUT: D21.1 R34.2 U14.6 | length 830.9
  Top Layer w10: U14.6@1939.13,920 2295,920 2341,874 2571,874 2588.31,856.69 D21.1@2588.31,797.99 2680.87,797.99 R34.2@2683.86,795
CTS_OUT_1: U14.23 U15.6 | length 781.2
  Top Layer w10: U15.6@924.49,740 1116,740 1215,839 v1(1215,922) ; v2(1469,920) U14.23@1580.87,920
  Bottom Layer w10: v1(1215,922) 1467,922 v2(1469,920)
CTSIN: J2.3 U7.2 | length 696.1
  Top Layer w10: J2.3@155,2200 275,2200 530,1945 U7.2@745.51,1945
CTSOUT: J4.4 U15.3 | length 648
  Top Layer w10: J4.4@160,915 390,915 565,740 U15.3@735.51,740
DCD_IN: D11.1 R19.1 U6.6 | length 921.5
  Top Layer w10: U6.6@1924.13,2010 2160,2010 2345,2195 2565,2195 2588.31,2218.31 D11.1@2588.31,2287.99 2590.32,2290 R19.1@2688.86,2290
DCD_IN_1: U6.17 U8.3 | length 1273.6
  Top Layer w10: U8.3@1024.13,1475 1123,1475 1178,1530 v1(1219,1530) 1219,2189 1340,2310 U6.17@1565.87,2310
DCD_OUT: D15.1 R31.2 U14.10 | length 1134.8
  Top Layer w10: U14.10@1939.13,1120 2210,1120 2385,1295 2385,1515 2425,1555 2580,1555 2588.31,1563.31 D15.1@2588.31,1632.99 2681.85,1632.99 R31.2@2688.86,1640
DCD_OUT_1: U14.19 U16.13 | length 1201
  Top Layer w10: U16.13@1019.13,390 1187,390 1270,473 1270,1041 v1(1354,1125) ; v2(1492,1123) 1495,1120 U14.19@1580.87,1120
  Bottom Layer w10: v1(1354,1125) 1490,1125 v2(1492,1123)
DCDIN: J2.5 U8.14 | length 1115.8
  Top Layer w10: J2.5@155,2000 100,2000 55,1955 55,1635 100,1590 445,1590 560,1475 U8.14@665.87,1475
DCDOUT: J4.7 U16.4 | length 594.1
  Top Layer w10: J4.7@160,615 310,615 535,390 U16.4@660.87,390
DSR_IN: D12.1 R20.1 U6.7 | length 968.3
  Top Layer w10: U6.7@1924.13,2060 2037,2060 2355,2378 2573,2378 2588.31,2393.31 D12.1@2588.31,2457.99 2686.85,2457.99 R20.1@2688.86,2460
DSR_IN_1: U6.16 U8.4 | length 1243.2
  Top Layer w10: U8.4@1024.13,1525 1130,1525 1201,1596 1201,2203 1358,2360 v1(1477,2360) U6.16@1565.87,2360
DSR_OUT: D19.1 R32.2 U14.7 | length 872.6
  Top Layer w10: U14.7@1939.13,970 2240,970 2330,1060 2558.84,1060 2588.31,1030.53 D19.1@2588.31,957.99 2686.85,957.99 R32.2@2688.86,960
DSR_OUT_1: U14.22 U16.14 | length 1444.9
  Top Layer w10: U16.14@1019.13,440 1199,440 1252,493 1252,1071 v1(1279,1098) ; U14.22@1580.87,971 v2(1690,971)
  Bottom Layer w10: v1(1279,1098) 1285,1092 1571,1092 1690,973 v2(1690,971)
DSRIN: J2.6 U8.13 | length 910.3
  Top Layer w10: J2.6@155,1900 76,1821 76,1674 140,1610 467.37,1610 552.37,1525 U8.13@665.87,1525
DSROUT: J4.6 U16.3 | length 614.8
  Top Layer w10: J4.6@160,715 250,715 525,440 U16.3@660.87,440
DTE_RX: D7.1 R21.1 U6.4 | length 835.2
  Top Layer w10: U6.4@1924.13,1910 2195,1910 2223,1882 2574,1882 2588.31,1896.31 D7.1@2588.31,1947.99 2685.87,1947.99 R21.1@2688.86,1945
DTE_RX_IN: J2.1 U5.2 | length 675.4
  Top Layer w10: J2.1@155,2400 160,2395 290,2395 490,2195 U5.2@745.51,2195
DTE_RX_IN_1: U5.7 U6.19 | length 931.8
  Top Layer w10: U5.7@934.49,2195 v1(1023,2195) ; U6.19@1565.87,2210 1620,2210 v2(1655,2245)
  Bottom Layer w10: v1(1023,2195) 1023,2176.64 1056.64,2143 1253.53,2143 1395.53,2285 1570,2285 1610,2245 v2(1655,2245)
DTE_TX: D8.1 R23.1 U6.9 | length 1155.8
  Top Layer w10: U6.9@1924.13,2160 2066.91,2160 2406,2499.09 2406,2664 2480.31,2738.31 2566.61,2738.31 2588.31,2760 D8.1@2588.31,2802.99 2681.85,2802.99 R23.1@2688.86,2810
DTE_TX_OUT: J2.2 U5.3 | length 654.7
  Top Layer w10: J2.2@155,2300 340,2300 495,2145 U5.3@745.51,2145
DTE_TX_OUT_1: U5.6 U6.14 | length 1306.3
  Top Layer w10: U5.6@934.49,2145 1038,2145 v1(1070,2177) ; U6.14@1924.13,2409 2008,2409 v2(2022,2423)
  Bottom Layer w10: v1(1070,2177) 1262.07,2177 1388.07,2303 1390.53,2303 1398.53,2311 1739,2311 1851,2423 v2(2022,2423)
DTR_IN: D18.1 R35.2 U14.11 | length 1510.2
  Top Layer w10: v2(1864,1170) U14.11@1939.13,1170 ; v2(2390,715) 2450,655 2450,564.01 2415,529.01 2415,410 2470,355 2570,355 2588.31,336.69 D18.1@2588.31,272.99 2685.87,272.99 R35.2@2688.86,270
  Bottom Layer w10: v2(1864,1170) 1930,1170 2390,710 v2(2390,715)
DTR_IN_1: U14.18 U16.11 | length 1281.2
  Top Layer w10: U16.11@1019.13,290 v1(1225,290) 1307,372 1307,978 1499,1170 U14.18@1580.87,1170
DTR_OUT: D14.1 R25.1 U6.11 | length 1455.1
  Top Layer w10: U6.11@1924.13,2260 2116,2260 2370,2514 2370,2688 2410.46,2728.46 2410.46,3045.46 2450,3085 2575,3085 2588.31,3098.31 D14.1@2588.31,3152.99 2686.85,3152.99 R25.1@2688.86,3155
DTR_OUT_1: U6.12 U8.6 | length 1534.6
  Top Layer w10: U8.6@1024.13,1625 1093,1625 1101,1617 v1(1108,1617) ; U6.12@1924.13,2311 v2(1995,2311)
  Bottom Layer w10: v1(1108,1617) 1108,1959.99 1181,2032.99 1181,2035.01 1610.01,2035.01 1886,2311 v2(1995,2311)
DTRIN: J4.5 U16.6 | length 1007.7
  Top Layer w10: J4.5@160,815 90,745 90,490 120,460 390,460 560,290 U16.6@660.87,290
DTROUT: J2.8 U8.11 | length 541.9
  Top Layer w10: J2.8@155,1700 440,1700 515,1625 U8.11@665.87,1625
FORCEOFF: R2.1 R53.2 U6.22 | length 269.2
  Top Layer w10: R53.2@1321.5,2051 1324.2,2048.3 1420.8,2048.3 R2.1@1448.5,2076 ; R2.1@1452.5,2080 R2.1@1448.5,2076 ; U6.22@1565.87,2060 1499,2060 1483,2076 R2.1@1448.5,2076
FORCEOFF_1: R10.1 R55.2 U14.14 | length 215.1
  Top Layer w10: U14.14@1939.13,1320 1995,1320 2032,1357 R10.1@2068.5,1357 2068.5,1426 R55.2@2069.5,1427
FORCEON: R1.1 R52.1 U6.23 | length 293.5
  Top Layer w10: R52.1@1317.5,1972 R52.1@1317.5,1984.5 ; R52.1@1321.5,1986 1321.5,1986.76 1364.43,2029.7 1414.57,2029.7 1446.27,1998 R1.1@1452.5,1998 1493,1998 1505,2010 U6.23@1565.87,2010
FORCEON_1: R9.1 R54.2 U14.13 | length 195.2
  Top Layer w10: U14.13@1939.13,1270 2067.5,1270 R9.1@2068.5,1271 2068.5,1207 R54.2@2067.5,1206
GND1: C1.2 C4.2 C10.2 C12.2 C16.2 C21.2 C23.1 C24.1 C32.2 C33.2 C34.2 C35.2 C36.2 D4.1 D5.2 H1.1 J5.1 J6.1 J6.2 TP4.1 U5.4 U7.4 U8.9 U8.15 U13.4 U15.4 U16.2 U16.8 U18.4 U18.5 U19.2 | length 1710.6
  Top Layer w20: J5.1@150,2765 203.74,2765 225.24,2786.5 C32.2@330,2786.5 v1(330,2840) ; C33.2@400,2786.5 v1(400,2840) ; v1(405,2545) C35.2@496.5,2545 ; v1(510,1425) 511.5,1426.5 C10.2@555,1426.5 556.5,1425 U8.15@665.87,1425 ; C21.2@565,606.5 v1(565,655) ; C12.2@568.5,1185 568.5,1238.5 v1(570,1240) ; C16.2@578.5,840 578.5,888.5 v1(580,890) ; v1(581,173) 598,190 U16.8@660.87,190 ; C4.2@583.5,1995 583.5,2043.5 v1(585,2045) ; v1(587,481) 596,490 U16.2@660.87,490 ; C1.2@588.5,2250 588.5,2298.5 v1(590,2300) ; v1(617,1781) 616,1780 616,1734 625,1725 U8.9@665.87,1725 ; v1(650,1036) 651,1035 U13.4@735.51,1035 ; v1(654,690) U15.4@735.51,690 ; v1(670,2095) U5.4@745.51,2095 ; v1(676,1845) U7.4@745.51,1845 ; v1(749,2883) 749,2899 765,2915 D4.1@792.52,2915 795,2912.52 C34.2@795,2831.5 ; C36.2@861.5,2630 v1(925,2630) ; C24.1@985,2983.5 1023.5,2983.5 v1(1030,2990) ; D5.2@1074.47,2540 1074.47,2609.47 v1(1075,2610)
  other v1: 525,3215 590,3215 640,3215
GND2: C2.2 C5.2 C7.2 C8.2 C9.2 C11.2 C13.2 C17.2 C18.2 C19.2 C20.2 C22.2 C25.2 C26.2 C27.2 C28.2 C29.2 C30.2 C31.2 D23.2 J1.5 J3.5 R37.1 R38.1 R52.2 R53.1 R54.1 R55.1 T1.5 TP5.1 U5.5 U6.25 U7.5 U8.2 U8.8 U13.5 U14.2 U15.5 U16.9 U16.15 U17.2 | length 3326.1
  Top Layer w15: v1(1085,890) 1086.5,888.5 C17.2@1086.5,840 ; C18.2@2101.5,820 2145,820 v1(2155,830)
  Top Layer w20: U15.5@924.49,690 978,690 v1(992,676) ; U13.5@924.49,1035 972,1035 1028,979 v1(1030,979) ; U7.5@934.49,1845 939,1840.49 v1(939,1808) ; U5.5@934.49,2095 937,2092.49 v1(937,2055) 980,2055 1014,2089 1108,2089 v1(1152,2045) 1146.5,2045 C5.2@1096.5,1995 ; v1(1003,1774) 1024.13,1752.87 U8.8@1024.13,1725 ; v1(1019,151) 1019.13,151.13 U16.9@1019.13,190 ; U16.15@1019.13,490 1094,490 1100.5,483.5 C22.2@1130,483.5 1176.5,483.5 v1(1181,479) ; U8.2@1024.13,1425 1126.5,1425 C11.2@1130,1421.5 1173.5,1421.5 v1(1178,1425.99) ; C2.2@1091.5,2245 1095,2248.5 v1(1095,2290) ; C13.2@1096.5,1185 1130.5,1219 v1(1154,1219) ; R53.1@1258.5,2051 R52.2@1258.5,1986 1258.5,1943.5 v1(1259,1943) ; v1(1338,1799) 1339,1800 C8.2@1388.5,1800 C9.2@1388.5,1870 ; v1(1352,693) 1352,695 C19.2@1398.5,695 C20.2@1398.5,770 ; U6.25@1565.87,1910 v1(1655,1910) ; C27.2@1741.5,2675 1741.5,2581.5 v1(1747,2576) ; U14.2@1939.13,720 1989,720 v1(2008,701) ; v1@2017.91,3138.09 v1(2020,3136) ; C26.2@2030,3017.5 2030,3076 v1(2031,3077) ; C7.2@2091.5,1860 v1(2145,1860) ; C25.2@2100,3017.5 v1(2100,3071) ; v1(2125,2530) C31.2@2185,2530 ; R54.1@2130.5,1206 v1(2182,1206) ; R55.1@2132.5,1427 2186,1427 v1(2188,1425) ; C28.2@2260,2675 v1(2315,2675)
  Top Layer w25: 1370,3066 1411,3025 T1.5@1449.84,3025
  Top Layer w30: 1370,3066 1370,3234 1408,3272 1730,3272 1801,3201 1801,3110.11 1802.3,3108.8 1821.4,3108.8 1850.68,3138.09 C29.2@1910,3138.09 v1@2017.91,3138.09
  other v1: 2255,540 2170,545 1685,580 1835,580 2255,635 2170,640 2170,705 1800,815 1800,1095 1680,1416 1803,1419 2275,1450 2340,1450 1684,1553 1807,1556 1683,1667 1806,1670 2340,1732.99 2859,1759 2808,1760 2335,1817.99 2807,1818 2857,1819 1695,2029 1769,2032 1753,2416 1678,2417 1649,2631 1649,2685 2560,3266 2760,3267 2960,3271 2560,3325 2760,3340 2960,3345 2560,3400 2760,3400 2960,3410
GND3: C37.1 C38.1 D6.1 D7.2 D8.2 D9.2 D10.2 D11.2 D12.2 D13.2 D14.2 D15.2 D16.2 D17.2 D18.2 D19.2 D20.2 D21.2 D22.2 L1.2 L2.2 R37.2 R38.2 | length 901.7
  Top Layer w20: v1(2450,1212.99) D16.2@2501.69,1212.99 ; v1(2450,1467.99) D20.2@2501.69,1467.99 ; v1(2450,1632.99) D15.2@2501.69,1632.99 ; v1@2451.46,1947.99 D7.2@2503.15,1947.99 ; v1@2451.46,2117.99 D10.2@2501.69,2117.99 ; v1@2451.46,2287.99 D11.2@2501.69,2287.99 ; v1@2451.46,2457.99 v1(2457.46,2457.99) D12.2@2501.69,2457.99 ; v1@2451.46,2637.99 v1(2457.46,2637.99) D13.2@2501.69,2637.99 ; v1@2451.46,2802.99 v1(2457.46,2802.99) D8.2@2501.69,2802.99 ; v1@2451.46,2977.99 v1(2457.46,2977.99) D9.2@2501.69,2977.99 ; v1@2451.46,3152.99 v1(2457.46,3152.99) D14.2@2501.69,3152.99 ; v1(2455,800) 2457.01,797.99 D21.2@2501.69,797.99 ; v1(2455,960) 2457.01,957.99 D19.2@2501.69,957.99 ; v1(2460,100) 2462.01,97.99 D22.2@2501.69,97.99 ; v1(2460,275) 2462.01,272.99 D18.2@2501.69,272.99 ; v1(2460,533) 2462.01,530.99 D17.2@2501.69,530.99 ; L2.2@3067,237 3126,237 3129,240 v1(3129,244) ; v1(3145,3170) 3146,3169 L1.2@3146,3117
  other v1: 3140,203 2330,270 2356,323 2300,325 2356,393 2300,395 2540,1728 2611,1728 2578,1779 2611,1827 2540,1827.99 2457.46,1947.99 2457.46,2117.99 2457.46,2287.99 3075,3163 3110,3200
GND_EARTH: C37.2 C38.2 D6.2 H4.1
INVALID: TP7.1 U6.21 | length 127.8
  Top Layer w10: TP7.1@1456,2152 1456,2151 1497,2110 U6.21@1565.87,2110
INVALID_1: TP6.1 U14.15 | length 176.3
  Top Layer w10: TP6.1@1467,1400 1467,1350 1497,1320 U14.15@1580.87,1320
NetC3_1: C3.1 U6.1 | length 110.6
  Top Layer w10: U6.1@1924.13,1760 1925.13,1761 1976,1761 1990,1775 C3.1@2028.5,1775
NetC3_2: C3.2 U6.2 | length 181.9
  Top Layer w10: U6.2@1924.13,1810 2056.5,1810 C3.2@2091.5,1775
NetC6_1: C6.1 U6.28 | length 128.9
  Top Layer w10: C6.1@1451.5,1725 1482,1725 1516,1759 1564.87,1759 U6.28@1565.87,1760
NetC6_2: C6.2 U6.24 | length 407
  Top Layer w10: v2(1343,1725) C6.2@1388.5,1725 ; v2(1499,1950) 1509,1960 U6.24@1565.87,1960
  Bottom Layer w10: 1499,1883 1500,1882
  Bottom Layer w15: v2(1343,1725) 1500,1882 ; 1499,1883 v2(1499,1950)
NetC7_1: C7.1 U6.3 | length 104.4
  Top Layer w10: U6.3@1924.13,1860 C7.1@2028.5,1860
NetC8_1: C8.1 U6.27 | length 118.5
  Top Layer w10: C8.1@1451.5,1800 1495,1800 1505,1810 U6.27@1565.87,1810
NetC9_1: C9.1 R51.2 U6.26 | length 182.9
  Top Layer w20: R51.2@1452.5,1934 1452.5,1871 C9.1@1451.5,1870 1494,1870 1504,1860 U6.26@1565.87,1860
NetC14_1: C14.1 U14.28 | length 138
  Top Layer w10: C14.1@1461.5,625 1506.5,670 U14.28@1580.87,670
NetC14_2: C14.2 U14.25 | length 367.8
  Top Layer w10: v2(1357,625) C14.2@1398.5,625 ; v2(1515,820) U14.25@1580.87,820
  Bottom Layer w15: v2(1357,625) 1515,783 v2(1515,820)
NetC15_1: C15.1 U14.1 | length 137.7
  Top Layer w10: U14.1@1940,665 2021,665 2039.5,683.5 C15.1@2070,683.5
NetC15_2: C15.2 U14.3 | length 139.7
  Top Layer w10: U14.3@1940,770 2003,770 2026.5,746.5 C15.2@2070,746.5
